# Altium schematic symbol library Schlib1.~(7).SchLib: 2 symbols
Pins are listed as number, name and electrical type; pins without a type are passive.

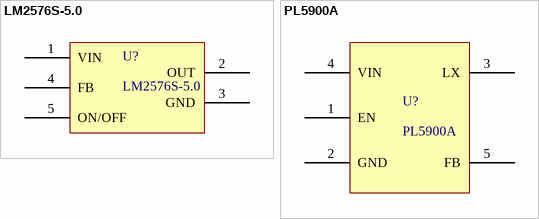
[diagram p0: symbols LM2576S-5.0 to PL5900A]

## LM2576S-5.0
designator U?
footprint TO263-5A (263，5脚晶体管)
pins: 1 VIN, 2 OUT, 3 GND, 4 FB, 5 ON/OFF

## PL5900A
designator U?
footprint SOT23-5L (3x1.6x1.1mm(长宽高))
pins: 1 EN, 2 GND, 3 LX, 4 VIN, 5 FB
